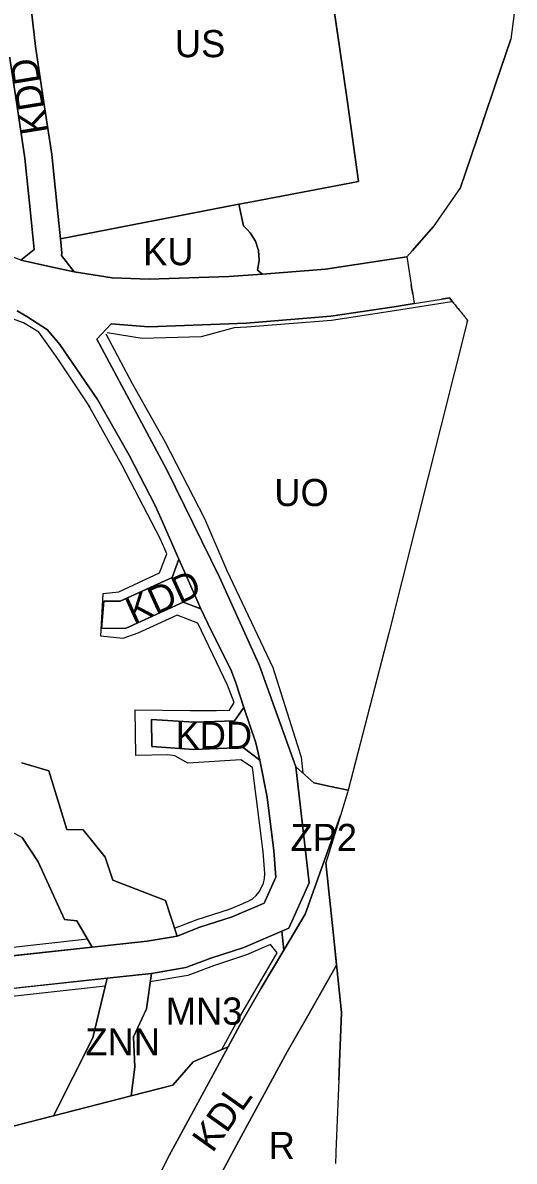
# Model space of a CAD drawing. Extents: x 7417187 to 7419415, y 5539178 to 5540826.
# Drawn here: x 7419069 to 7419250.2, y 5539426.9 to 5539846.6 of the extents above; entities that cross this region are included whole.
import ezdxf

# ---------------------------------------------------------------- set-up
doc = ezdxf.new("R2010")
doc.units = 0
for name, color, linetype in [('linie_rozgraniczajace', 7, 'Continuous'), ('linie_zabudowy_nieprzekraczalne', 7, 'Continuous'), ('linie_zabudowy_obowiazujace', 7, 'Continuous'), ('oznaczenia_przeznaczen', 7, 'Continuous')]:
    doc.layers.add(name, color=color, linetype=linetype)

msp = doc.modelspace()

# ---------------------------------------------------------------- linework, layer by layer
at = {"layer": 'linie_rozgraniczajace'}
for p, q in [((7419185.79, 5539837.72), (7419182.59, 5539859.62)), ((7419250.22, 5539850.01), (7419249.03, 5539840.61)), ((7419249.03, 5539840.61), (7419239.2, 5539811.66)), ((7419249.03, 5539840.61), (7419243.65, 5539825.05)), ((7419243.65, 5539825.05), (7419249.03, 5539840.61)), ((7419188.75, 5539817.33), (7419185.79, 5539837.72)), ((7419243.65, 5539825.05), (7419238.41, 5539809.33)), ((7419238.41, 5539809.33), (7419243.65, 5539825.05)), ((7419192.83, 5539788.1), (7419188.75, 5539817.33)), ((7419239.2, 5539811.66), (7419230.47, 5539785.9)), ((7419238.4, 5539809.33), (7419230.47, 5539785.9)), ((7419230.47, 5539785.9), (7419238.41, 5539809.33)), ((7419238.41, 5539809.33), (7419238.4, 5539809.33)), ((7419239.2, 5539811.66), (7419238.41, 5539809.33)), ((7419238.41, 5539809.33), (7419239.2, 5539811.66)), ((7419151.48, 5539780.24), (7419192.83, 5539788.1)), ((7419230.47, 5539785.9), (7419220.38, 5539771.38)), ((7419148.72, 5539779.71), (7419151.48, 5539780.24)), ((7419150.4, 5539771.72), (7419148.72, 5539779.71)), ((7419151.74, 5539770.45), (7419150.4, 5539771.72)), ((7419220.38, 5539771.38), (7419212.67, 5539762.66)), ((7419212.67, 5539762.66), (7419220.38, 5539771.38)), ((7419220.38, 5539771.38), (7419212.67, 5539762.66)), ((7419152.85, 5539769.13), (7419151.74, 5539770.45)), ((7419154.8, 5539766.08), (7419152.85, 5539769.13)), ((7419155.96, 5539762.62), (7419154.8, 5539766.08)), ((7419156.2, 5539759), (7419155.96, 5539762.62)), ((7419212.67, 5539762.66), (7419210.64, 5539760.37)), ((7419212.67, 5539762.66), (7419210.64, 5539760.37)), ((7419210.64, 5539760.37), (7419212.67, 5539762.66)), ((7419068.31, 5539759.14), (7419081.09, 5539756.29)), ((7419155.56, 5539755.42), (7419156.2, 5539759)), ((7419203.23, 5539759.2), (7419180.59, 5539755.78)), ((7419180.59, 5539755.78), (7419203.23, 5539759.2)), ((7419210.64, 5539760.37), (7419203.23, 5539759.2)), ((7419203.23, 5539759.2), (7419210.64, 5539760.37)), ((7419210.64, 5539760.37), (7419210.64, 5539760.37)), ((7419210.64, 5539760.37), (7419212.23, 5539750.1)), ((7419081.09, 5539756.29), (7419087.96, 5539754.81)), ((7419087.96, 5539754.81), (7419102.03, 5539752.63)), ((7419144.94, 5539753.11), (7419157.45, 5539753.88)), ((7419157.45, 5539753.88), (7419155.56, 5539755.42)), ((7419180.59, 5539755.78), (7419157.45, 5539753.88)), ((7419157.45, 5539753.88), (7419180.59, 5539755.78)), ((7419102.03, 5539752.63), (7419115.61, 5539752.05)), ((7419115.61, 5539752.05), (7419144.94, 5539753.11)), ((7419212.23, 5539750.1), (7419212.5, 5539748.32)), ((7419212.5, 5539748.32), (7419212.23, 5539750.1)), ((7419212.23, 5539750.1), (7419212.5, 5539748.32)), ((7419212.5, 5539748.32), (7419212.57, 5539747.89)), ((7419212.5, 5539748.32), (7419212.5, 5539748.32)), ((7419212.5, 5539748.32), (7419212.78, 5539746.53)), ((7419212.57, 5539747.89), (7419212.5, 5539748.32)), ((7419212.5, 5539748.32), (7419212.5, 5539748.32)), ((7419212.57, 5539747.89), (7419212.78, 5539746.53)), ((7419212.78, 5539746.53), (7419212.57, 5539747.89)), ((7419212.78, 5539746.53), (7419213.31, 5539743.08)), ((7419182.61, 5539738.39), (7419205.91, 5539741.9)), ((7419205.91, 5539741.9), (7419182.61, 5539738.39)), ((7419205.91, 5539741.9), (7419213.31, 5539743.08)), ((7419213.31, 5539743.08), (7419205.91, 5539741.9)), ((7419213.31, 5539743.08), (7419223.44, 5539744.68)), ((7419226.32, 5539745.14), (7419223.44, 5539744.68)), ((7419223.44, 5539744.68), (7419226.32, 5539745.14)), ((7419223.44, 5539744.68), (7419226.32, 5539745.14)), ((7419226.32, 5539745.14), (7419227.56, 5539743.62)), ((7419227.56, 5539743.62), (7419226.32, 5539745.14)), ((7419226.32, 5539745.14), (7419227.56, 5539743.62)), ((7419070.47, 5539738.34), (7419066.99, 5539740.46)), ((7419078.1, 5539733.36), (7419070.47, 5539738.34)), ((7419151.5, 5539735.84), (7419182.61, 5539738.39)), ((7419182.61, 5539738.39), (7419151.5, 5539735.84)), ((7419078.69, 5539732.77), (7419078.1, 5539733.36)), ((7419096.29, 5539729.92), (7419101.61, 5539735.67)), ((7419101.61, 5539735.67), (7419096.29, 5539729.92)), ((7419101.61, 5539735.67), (7419115.55, 5539734.54)), ((7419115.55, 5539734.54), (7419101.61, 5539735.67)), ((7419115.55, 5539734.54), (7419151.5, 5539735.84)), ((7419151.5, 5539735.84), (7419115.55, 5539734.54)), ((7419233.05, 5539736.9), (7419203.98, 5539621.51)), ((7419232.92, 5539736.36), (7419233.05, 5539736.9)), ((7419233.05, 5539736.9), (7419232.92, 5539736.36)), ((7419082.74, 5539728.03), (7419078.69, 5539732.77)), ((7419122.2, 5539681.79), (7419096.29, 5539729.92)), ((7419096.29, 5539729.92), (7419122.2, 5539681.79)), ((7419096.62, 5539707.66), (7419082.74, 5539728.03)), ((7419108.26, 5539687.19), (7419096.62, 5539707.66)), ((7419117.87, 5539668.61), (7419108.26, 5539687.19)), ((7419141.59, 5539642.25), (7419122.2, 5539681.79)), ((7419122.2, 5539681.79), (7419141.59, 5539642.25)), ((7419120.07, 5539663.68), (7419117.87, 5539668.61)), ((7419126.59, 5539648.79), (7419120.07, 5539663.68)), ((7419129.61, 5539641.91), (7419126.59, 5539648.79)), ((7419134.68, 5539630.5), (7419129.61, 5539641.91)), ((7419156.15, 5539609.87), (7419141.59, 5539642.25)), ((7419141.59, 5539642.25), (7419156.15, 5539609.87)), ((7419137.23, 5539625.11), (7419134.68, 5539630.5)), ((7419145.93, 5539607.5), (7419137.23, 5539625.11)), ((7419203.98, 5539621.51), (7419188.95, 5539563.64)), ((7419147.56, 5539603.2), (7419145.93, 5539607.5)), ((7419169.72, 5539572.23), (7419156.15, 5539609.87)), ((7419156.15, 5539609.87), (7419169.72, 5539572.23)), ((7419150.55, 5539594.21), (7419147.56, 5539603.2)), ((7419154.91, 5539581.15), (7419150.55, 5539594.21)), ((7419156.43, 5539574.71), (7419154.91, 5539581.15)), ((7419159.11, 5539561.16), (7419156.43, 5539574.71)), ((7419174.66, 5539529.52), (7419169.72, 5539572.23)), ((7419169.72, 5539572.23), (7419176.29, 5539566.44)), ((7419176.29, 5539566.44), (7419169.72, 5539572.23)), ((7419169.72, 5539572.23), (7419174.66, 5539529.52)), ((7419176.29, 5539566.44), (7419182.46, 5539565)), ((7419182.46, 5539565), (7419176.29, 5539566.44)), ((7419161.62, 5539541.32), (7419159.11, 5539561.16)), ((7419182.46, 5539565), (7419188.95, 5539563.64)), ((7419188.95, 5539563.64), (7419182.46, 5539565)), ((7419188.73, 5539562.78), (7419186.14, 5539554.35)), ((7419188.87, 5539563.33), (7419188.73, 5539562.78)), ((7419188.95, 5539563.64), (7419188.87, 5539563.33)), ((7419173.11, 5539517.95), (7419186.14, 5539554.35)), ((7419186.14, 5539554.35), (7419173.11, 5539517.95)), ((7419186.14, 5539554.35), (7419180.76, 5539536.85)), ((7419162.36, 5539531.63), (7419161.62, 5539541.32)), ((7419183.56, 5539510.19), (7419180.76, 5539536.85)), ((7419180.76, 5539536.85), (7419183.56, 5539510.19)), ((7419180.76, 5539536.85), (7419183.56, 5539510.19)), ((7419158.07, 5539522.01), (7419162.36, 5539531.63)), ((7419167.06, 5539512.81), (7419174.66, 5539529.52)), ((7419174.66, 5539529.52), (7419167.06, 5539512.81)), ((7419146.27, 5539516.97), (7419158.07, 5539522.01)), ((7419134.35, 5539513.13), (7419146.27, 5539516.97)), ((7419165.24, 5539504.66), (7419173.11, 5539517.95)), ((7419173.11, 5539517.95), (7419165.24, 5539504.66)), ((7419125.9, 5539509.91), (7419134.35, 5539513.13)), ((7419164.49, 5539511.71), (7419150.48, 5539505.72)), ((7419164.49, 5539511.71), (7419167.06, 5539512.81)), ((7419167.06, 5539512.81), (7419164.49, 5539511.71)), ((7419165.24, 5539504.66), (7419164.49, 5539511.71)), ((7419094.66, 5539505.83), (7419114.92, 5539508.02)), ((7419114.92, 5539508.02), (7419125.9, 5539509.91)), ((7419183.56, 5539510.19), (7419184.81, 5539498.34)), ((7419184.72, 5539499.16), (7419183.56, 5539510.19)), ((7419183.56, 5539510.19), (7419184.72, 5539499.16)), ((7419030.45, 5539498.89), (7419094.66, 5539505.83)), ((7419150.48, 5539505.72), (7419138.33, 5539501.8)), ((7419156.94, 5539490.64), (7419165.24, 5539504.66)), ((7419129.09, 5539498.28), (7419116.47, 5539496.14)), ((7419138.33, 5539501.8), (7419129.09, 5539498.28)), ((7419174.16, 5539480.46), (7419184.72, 5539499.16)), ((7419184.72, 5539499.16), (7419174.16, 5539480.46)), ((7419184.81, 5539498.34), (7419184.72, 5539499.16)), ((7419184.72, 5539499.16), (7419184.81, 5539498.34)), ((7419184.81, 5539498.34), (7419184.81, 5539498.34)), ((7419184.81, 5539498.34), (7419186.55, 5539481.75)), ((7419184.81, 5539498.34), (7419186.55, 5539481.75)), ((7419186.55, 5539481.75), (7419184.81, 5539498.34)), ((7419184.81, 5539498.34), (7419184.81, 5539498.34)), ((7419100.14, 5539494.37), (7419031.5, 5539486.94)), ((7419116.47, 5539496.14), (7419100.14, 5539494.37)), ((7419149.05, 5539477.04), (7419156.94, 5539490.64)), ((7419186.55, 5539481.75), (7419185.81, 5539463.44)), ((7419185.81, 5539463.44), (7419186.55, 5539481.75)), ((7419186.55, 5539481.75), (7419185.81, 5539463.44)), ((7419144.7, 5539469.02), (7419149.05, 5539477.04)), ((7419166.49, 5539467.25), (7419174.16, 5539480.46)), ((7419174.16, 5539480.46), (7419166.49, 5539467.25)), ((7419131.87, 5539463.51), (7419144.7, 5539469.02)), ((7419131.92, 5539445.48), (7419144.7, 5539469.02)), ((7419144.7, 5539469.02), (7419131.92, 5539445.48)), ((7419149.51, 5539435.97), (7419166.49, 5539467.25)), ((7419166.49, 5539467.25), (7419149.51, 5539435.97)), ((7419124.4, 5539454.87), (7419131.87, 5539463.51)), ((7419185.81, 5539463.44), (7419185.55, 5539456.87)), ((7419185.65, 5539459.37), (7419185.81, 5539463.44)), ((7419185.81, 5539463.44), (7419185.65, 5539459.37)), ((7419185.81, 5539463.44), (7419185.81, 5539463.44)), ((7419185.81, 5539463.44), (7419185.81, 5539463.44)), ((7419185.55, 5539456.87), (7419185.43, 5539453.92)), ((7419185.55, 5539456.87), (7419185.65, 5539459.37)), ((7419185.65, 5539459.37), (7419185.55, 5539456.87)), ((7419109.02, 5539450.95), (7419124.4, 5539454.87)), ((7419185.43, 5539453.92), (7419184.49, 5539430.39)), ((7419080.39, 5539443.66), (7419109.02, 5539450.95)), ((7419051.94, 5539436.41), (7419080.39, 5539443.66)), ((7419123.03, 5539428.98), (7419131.92, 5539445.48)), ((7419131.92, 5539445.48), (7419123.03, 5539428.98)), ((7419140.76, 5539419.72), (7419149.51, 5539435.97)), ((7419149.51, 5539435.97), (7419140.76, 5539419.72)), ((7419114.66, 5539412.44), (7419123.03, 5539428.98)), ((7419123.03, 5539428.98), (7419114.66, 5539412.44)), ((7419184.46, 5539429.71), (7419184.31, 5539426.08)), ((7419184.49, 5539430.39), (7419184.46, 5539429.71))]:
    msp.add_line(p, q, dxfattribs=at)
for points in [[(7419148.72, 5539779.71), (7419082.92, 5539766.9), (7419081.88, 5539777.49), (7419079.76, 5539798.03), (7419076.8, 5539817.26), (7419073.67, 5539837.92), (7419071.59, 5539856.29), (7419069.37, 5539875.06), (7419073.55, 5539881.54), (7419077.96, 5539882.95), (7419096.73, 5539890.23), (7419100.27, 5539892.48), (7419106.41, 5539894.54), (7419174.03, 5539917.24), (7419176.19, 5539903.36), (7419177.17, 5539896.99), (7419178.5, 5539887.94), (7419180.45, 5539874.45), (7419182.59, 5539859.62), (7419185.79, 5539837.72), (7419188.75, 5539817.33), (7419192.83, 5539788.1), (7419151.48, 5539780.24)], [(7419068.31, 5539759.14), (7419066.42, 5539759.83), (7419056.75, 5539763.59), (7419044.35, 5539765.68), (7419031.26, 5539767.62), (7419017.77, 5539768.42), (7419003.17, 5539768.16), (7418980.62, 5539766.28), (7418983.98, 5539784.4), (7418985.78, 5539789.71), (7418988.47, 5539793.43), (7419008.25, 5539805.73), (7419028.14, 5539818.06), (7419049.32, 5539828.49), (7419063.87, 5539835.91), (7419066.92, 5539815.75), (7419069.84, 5539796.75), (7419071.93, 5539776.49), (7419073.25, 5539763.02)], [(7419157.45, 5539753.88), (7419144.94, 5539753.11), (7419115.61, 5539752.05), (7419102.03, 5539752.63), (7419087.96, 5539754.81), (7419083.36, 5539760.85), (7419083.42, 5539761.8), (7419082.92, 5539766.9), (7419148.72, 5539779.71), (7419150.4, 5539771.72), (7419151.74, 5539770.45), (7419152.85, 5539769.13), (7419154.8, 5539766.08), (7419155.96, 5539762.62), (7419156.2, 5539759), (7419155.56, 5539755.42)], [(7419134.68, 5539630.5), (7419128.1, 5539632.99), (7419107.13, 5539623.4), (7419098.1, 5539623.34), (7419098.9, 5539633.34), (7419104.92, 5539633.38), (7419124.05, 5539642.13), (7419126.59, 5539648.79), (7419129.61, 5539641.91)], [(7419156.43, 5539574.71), (7419150.28, 5539579.39), (7419132.05, 5539578.7), (7419116.63, 5539579.73), (7419116.54, 5539589.76), (7419132.2, 5539588.72), (7419147.14, 5539589.28), (7419150.55, 5539594.21), (7419154.91, 5539581.15)], [(7419094.66, 5539505.83), (7419030.45, 5539498.89), (7419016.1, 5539497.93), (7419008.39, 5539501.79), (7418986.37, 5539535.74), (7418999.27, 5539541.42), (7419013.22, 5539546.11), (7419028.07, 5539547.89), (7419048.04, 5539549.49), (7419064.77, 5539548.4), (7419068.79, 5539546.21), (7419074.65, 5539537.21), (7419084.35, 5539516.01), (7419088.91, 5539515.5)], [(7419165.24, 5539504.66), (7419156.94, 5539490.64), (7419149.05, 5539477.04), (7419144.7, 5539469.02), (7419131.87, 5539463.51), (7419124.4, 5539454.87), (7419109.02, 5539450.95), (7419110.38, 5539461.58), (7419109.83, 5539472.72), (7419114.63, 5539483.05), (7419116.47, 5539496.14), (7419129.09, 5539498.28), (7419138.33, 5539501.8), (7419150.48, 5539505.72), (7419164.49, 5539511.71)], [(7419080.39, 5539443.66), (7419051.94, 5539436.41), (7418971.32, 5539424.46), (7418967.53, 5539421.53), (7418794.01, 5539413.71), (7418793.33, 5539428.77), (7418792.9, 5539443.79), (7418794.41, 5539443.84), (7418808.32, 5539447.35), (7418824.83, 5539456.31), (7418848.46, 5539469.21), (7418868.88, 5539478.97), (7418878, 5539481.56), (7418905.97, 5539484.62), (7418932.4, 5539485.28), (7418955.96, 5539481.86), (7419031.5, 5539486.94), (7419100.14, 5539494.37), (7419094.9, 5539472.32)], [(7419109.02, 5539450.95), (7419080.39, 5539443.66), (7419094.9, 5539472.32), (7419100.14, 5539494.37), (7419116.47, 5539496.14), (7419114.63, 5539483.05), (7419109.83, 5539472.72), (7419110.38, 5539461.58)]]:
    msp.add_lwpolyline(points, close=True, dxfattribs=at)
for points in [[(7419071.59, 5539856.29), (7419073.67, 5539837.92), (7419076.8, 5539817.26), (7419079.76, 5539798.03), (7419081.88, 5539777.49), (7419082.92, 5539766.9), (7419083.42, 5539761.8), (7419083.36, 5539760.85), (7419087.96, 5539754.81), (7419081.09, 5539756.29), (7419068.31, 5539759.14), (7419073.25, 5539763.02), (7419071.93, 5539776.49), (7419069.84, 5539796.75), (7419066.92, 5539815.75), (7419063.87, 5539835.91), (7419063.76, 5539836.61), (7419063.63, 5539837.78), (7419061.66, 5539855.14)], [(7419066.99, 5539740.46), (7419070.47, 5539738.34), (7419078.1, 5539733.36), (7419078.69, 5539732.77), (7419082.74, 5539728.03), (7419096.62, 5539707.66), (7419108.26, 5539687.19), (7419117.87, 5539668.61), (7419120.07, 5539663.68), (7419126.59, 5539648.79), (7419124.05, 5539642.13), (7419104.92, 5539633.38), (7419098.9, 5539633.34), (7419098.1, 5539623.34), (7419107.13, 5539623.4), (7419128.1, 5539632.99), (7419134.68, 5539630.5), (7419137.23, 5539625.11), (7419145.93, 5539607.5), (7419147.56, 5539603.2), (7419150.55, 5539594.21), (7419147.14, 5539589.28), (7419132.2, 5539588.72), (7419116.54, 5539589.76), (7419116.63, 5539579.73), (7419132.05, 5539578.7), (7419150.28, 5539579.39), (7419156.43, 5539574.71), (7419159.11, 5539561.16), (7419161.62, 5539541.32), (7419162.36, 5539531.63), (7419158.07, 5539522.01), (7419146.27, 5539516.97), (7419134.35, 5539513.13), (7419125.9, 5539509.91), (7419121.61, 5539522.96), (7419102.25, 5539530.46), (7419099.37, 5539538.97), (7419091.29, 5539549.03), (7419085.27, 5539549.24), (7419078.64, 5539570.81), (7419068.73, 5539573.74)], [(7419068.73, 5539573.74), (7419078.64, 5539570.81), (7419085.27, 5539549.24), (7419091.29, 5539549.03), (7419099.37, 5539538.97), (7419102.25, 5539530.46), (7419121.61, 5539522.96), (7419125.9, 5539509.91), (7419114.92, 5539508.02), (7419094.66, 5539505.83), (7419088.91, 5539515.5), (7419084.35, 5539516.01), (7419074.65, 5539537.21), (7419068.79, 5539546.21)]]:
    msp.add_lwpolyline(points, dxfattribs=at)
for points in [[(7419227.56, 5539743.62), (7419232.03, 5539738.15)], [(7419232.03, 5539738.15), (7419233.05, 5539736.9)]]:
    msp.add_open_spline(points, degree=1, dxfattribs=at)
at = {"layer": 'linie_zabudowy_nieprzekraczalne'}
msp.add_line((7419227.43, 5539743.79), (7419227.13, 5539743.75), dxfattribs=at)
for points in [[(7419227.13, 5539743.75), (7419206.14, 5539740.42), (7419182.79, 5539736.9), (7419151.6, 5539734.34), (7419146.98, 5539734.18), (7419134.83, 5539730.85), (7419113.05, 5539730.24), (7419100.2, 5539732.31)], [(7419069.31, 5539735.92), (7419058.96, 5539739.67)], [(7419074.92, 5539732.52), (7419069.31, 5539735.92)], [(7419081.68, 5539723.03), (7419074.92, 5539732.52)], [(7419099.64, 5539731.87), (7419109.38, 5539713.67), (7419121.37, 5539692.21), (7419136.05, 5539663.89), (7419144.22, 5539644.71), (7419161.25, 5539608.95), (7419171.66, 5539575.83), (7419172.25, 5539570)], [(7419093.76, 5539705.02), (7419081.68, 5539723.03)], [(7419122.08, 5539650.77), (7419119.76, 5539656.21), (7419105.52, 5539683.68), (7419093.59, 5539705.03), (7419093.27, 5539705.63)], [(7419119.46, 5539643.77), (7419122.08, 5539650.77)], [(7419125.94, 5539628.23), (7419111.4, 5539621.55), (7419105.97, 5539619.64), (7419097.85, 5539620.45), (7419098.66, 5539636.22), (7419104.48, 5539636.78), (7419119.46, 5539643.77)], [(7419133.53, 5539625.3), (7419125.94, 5539628.23)], [(7419146.98, 5539596.06), (7419144.46, 5539602.35), (7419133.53, 5539625.3)], [(7419145.19, 5539593.16), (7419146.98, 5539596.06)], [(7419149.45, 5539574.92), (7419129.9, 5539573.65), (7419125.04, 5539576.28), (7419122.36, 5539576.76), (7419110.67, 5539576.51), (7419110.5, 5539593.28), (7419130.76, 5539593.02), (7419140.4, 5539593.11), (7419145.19, 5539593.16)], [(7419153.68, 5539571.98), (7419149.45, 5539574.92)], [(7419158.24, 5539533), (7419157.64, 5539540.92), (7419153.68, 5539571.98)], [(7419124.97, 5539512.76), (7419133.36, 5539515.96), (7419145.22, 5539519.78), (7419150.47, 5539522.03)], [(7419160.31, 5539506.79), (7419151.54, 5539502.91), (7419139.33, 5539498.97), (7419129.88, 5539495.37), (7419116.03, 5539493)], [(7419162.78, 5539503.7), (7419160.31, 5539506.79)], [(7419142.45, 5539468.03), (7419147.75, 5539477.78), (7419162.78, 5539503.7)]]:
    msp.add_lwpolyline(points, dxfattribs=at)
msp.add_arc((7419147.05, 5539532.69), 11.2, 287.6982, 1.5925, dxfattribs=at)
at = {"layer": 'linie_zabudowy_obowiazujace'}
for points in [[(7419014.39, 5539500.82), (7419030.19, 5539501.88), (7419092.9, 5539508.81)], [(7419099.43, 5539491.41), (7419031.76, 5539483.95), (7418955.85, 5539478.85), (7418932.22, 5539482.27), (7418911.79, 5539481.77)]]:
    msp.add_lwpolyline(points, dxfattribs=at)

# ---------------------------------------------------------------- texts
at = {"layer": 'oznaczenia_przeznaczen'}
for s, p in [('US', (7419125.11, 5539833.92)), ('KU', (7419113.42, 5539757.23)), ('UO', (7419161.78, 5539668.41)), ('KDD', (7419125.35, 5539578.91)), ('ZP2', (7419167.72, 5539541.25)), ('MN3', (7419121.75, 5539477.24)), ('ZNN', (7419092.11, 5539465.92)), ('R', (7419159.71, 5539427.67))]:
    msp.add_text(s, height=10, dxfattribs=at).set_placement(p)
for s, rotation, p in [('KDD', 99.2243, (7419078.58, 5539806.31)), ('KDD', 24.4224, (7419109.96, 5539624.51)), ('KDL', 54.5236, (7419138.97, 5539429.66))]:
    msp.add_text(s, height=10, rotation=rotation, dxfattribs=at).set_placement(p)

doc.saveas('drawing.dxf')
